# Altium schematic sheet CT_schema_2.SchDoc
size 313 x 200 mm
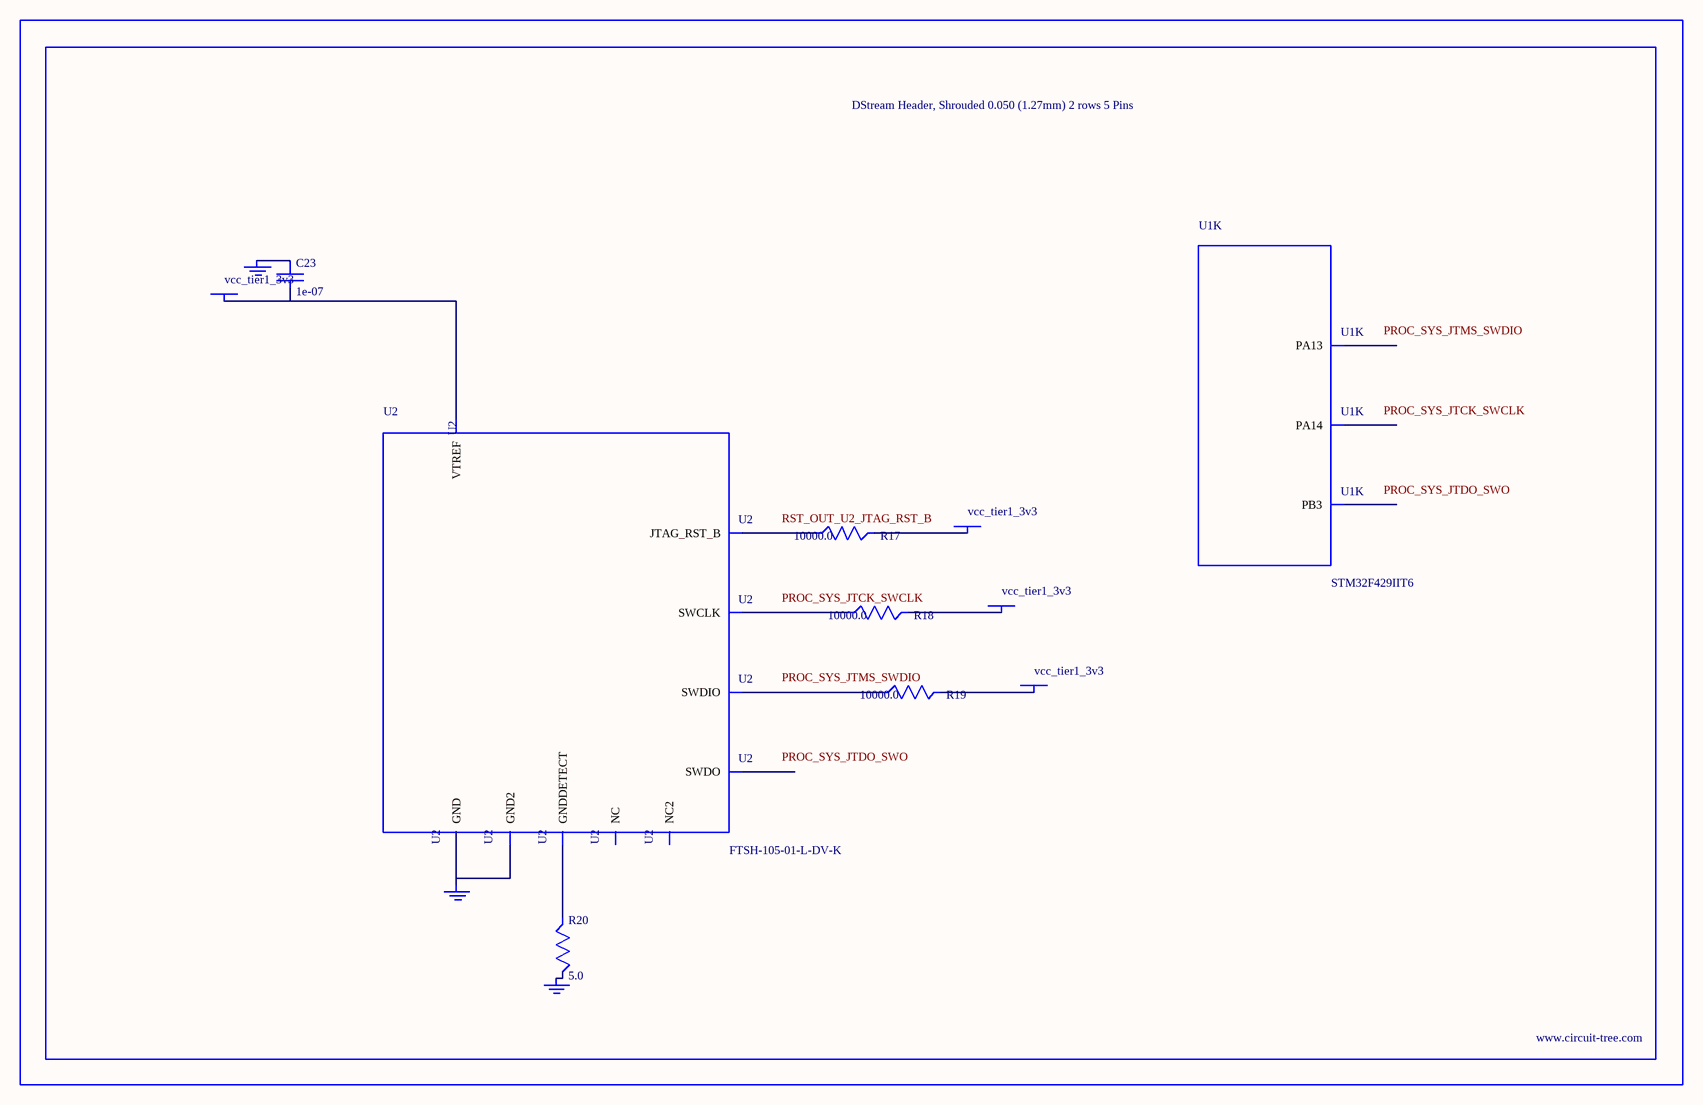
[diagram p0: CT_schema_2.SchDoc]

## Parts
BORDER1  (no value)
C23  1e-07  [C0402]
GND_INSTANCE_1_0  (no value)
GND_INSTANCE_1_1  (no value)
GND_INSTANCE_1_2  (no value)
POWER_INSTANCE_1_0  vcc_tier1_3v3
POWER_INSTANCE_1_1  vcc_tier1_3v3
POWER_INSTANCE_1_2  vcc_tier1_3v3
POWER_INSTANCE_1_3  vcc_tier1_3v3
R17  10000.0  [R0603]
R18  10000.0  [R0603]
R19  10000.0  [R0603]
R20  5.0  [R0603]
U1  STM32F429IIT6  [LQFP176]  (part K of 15)
U2  FTSH-105-01-L-DV-K  [SAMTEC_FTSH-105-01-L-DV-K]

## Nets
NetC23_1: C23.1 GND_INSTANCE_1_0.0(GND)
NetC23_2: C23.2 POWER_INSTANCE_1_0.0(PWR) U2.1(VTREF)
NetGND_INSTANCE_1_1_0: GND_INSTANCE_1_1.0(GND) R20.2
NetGND_INSTANCE_1_2_0: GND_INSTANCE_1_2.0(GND) U2.3(GND) U2.5(GND2)
NetPOWER_INSTANCE_1_1_0: POWER_INSTANCE_1_1.0(PWR) R19.2
NetPOWER_INSTANCE_1_2_0: POWER_INSTANCE_1_2.0(PWR) R18.2
NetPOWER_INSTANCE_1_3_0: POWER_INSTANCE_1_3.0(PWR) R17.2
NetR17_1: R17.1 U2.10(JTAG_RST_B)
NetR18_1: R18.1 U2.4(SWCLK)
NetR19_1: R19.1 U2.2(SWDIO)
NetR20_1: R20.1 U2.9(GNDDETECT)

Not connected (* = marked no-connect by the designer): U1 124(PA13) 137(PA14) 161(PB3); U2 6(SWDO) 7(NC) 8(NC2)

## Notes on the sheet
- Labels drawn without touching a wire or pin: PROC_SYS_JTCK_SWCLK, PROC_SYS_JTDO_SWO, PROC_SYS_JTMS_SWDIO, RST_OUT_U2_JTAG_RST_B

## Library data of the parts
BORDER1 = BORDER_PAGE1
C23 = C0402C104K3RACTU
GND_INSTANCE_1_0-GND_INSTANCE_1_2 = GND
POWER_INSTANCE_1_0-POWER_INSTANCE_1_3 = PWR
R17-R19 = RC0603JR-0710KL
R20 = ERJ-3GEYJ5R1V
